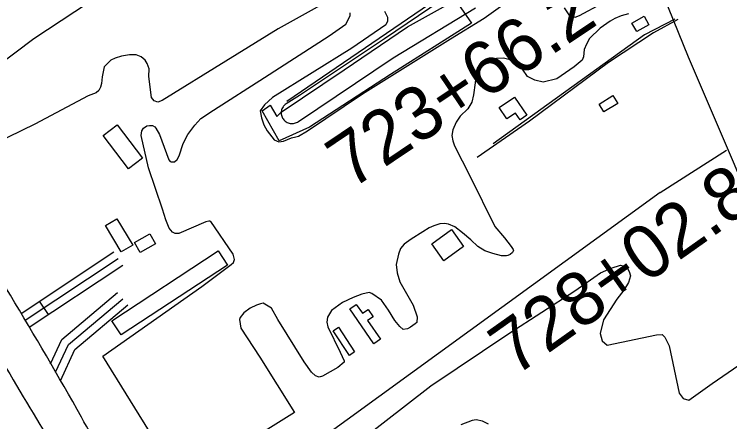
# Model space of a CAD drawing. Extents: x 3812694 to 3850888, y 319753 to 345638.
# Drawn here: x 3830119 to 3831459, y 329429 to 330193 of the extents above; entities that cross this region are included whole.
import ezdxf

# ---------------------------------------------------------------- set-up
doc = ezdxf.new("R2010")
doc.units = 0
for name, color, linetype in [('V-BLDG-OTLN', 7, 'Continuous'), ('V-RIVR-EDGE', 7, 'Continuous'), ('V-ROAD-CNTR', 7, 'Continuous'), ('V-SITE-OTLN', 7, 'Continuous'), ('V-SITE-VEGE', 7, 'Continuous'), ('V-SURV-IDEN', 7, 'Continuous')]:
    doc.layers.add(name, color=color, linetype=linetype)

msp = doc.modelspace()

# ---------------------------------------------------------------- linework, layer by layer
at = {"layer": 'V-BLDG-OTLN'}
for points in [[(3831275.7, 330176.7), (3831298.5, 330189.6), (3831307.4, 330173.8), (3831284.7, 330160.9)], [(3831027.1, 330018.4), (3831055.7, 330038.1), (3831079.1, 330004.1), (3831066.3, 329995.3), (3831057.6, 330008.1), (3831041.7, 329997.2)], [(3831214.2, 330024.8), (3831240.1, 330040.9), (3831249.2, 330026.2), (3831223.3, 330010.2)], [(3830311.3, 329985.7), (3830358.9, 329923.4), (3830333, 329903.6), (3830285.3, 329965.9)], [(3830311.2, 329809.9), (3830340.6, 329760.1), (3830319.3, 329747.6), (3830289.9, 329797.4)], [(3830383.2, 329762.9), (3830354.5, 329746.8), (3830344.1, 329765.4), (3830372.8, 329781.5)], [(3830900.8, 329762.9), (3830937.6, 329789.4), (3830960.5, 329757.6), (3830923.6, 329731.1)], [(3830301.4, 329618.5), (3830500.6, 329749.4), (3830518, 329723), (3830318.8, 329592.1)], [(3830792.2, 329575.3), (3830747.3, 329640.8), (3830759.4, 329649.2), (3830770.9, 329632.5), (3830781.5, 329639.8), (3830791, 329626), (3830780.5, 329618.7), (3830804.5, 329583.8)], [(3830725.9, 329606.2), (3830756.4, 329559.9), (3830746.7, 329553.5), (3830716.2, 329599.8)]]:
    msp.add_lwpolyline(points, close=True, dxfattribs=at)
at = {"layer": 'V-RIVR-EDGE'}
msp.add_spline([(3829949.6, 341433.3), (3829909, 341404.5), (3829896.7, 341391), (3829892.8, 341380.1), (3829894.1, 341369.2), (3829900.5, 341358.9), (3829915.9, 341346.6), (3829921.7, 341337.6), (3829921, 341333.1), (3829918.4, 341331.2), (3829912, 341326.7), (3829904.3, 341324.2), (3829899.1, 341318.4), (3829898.4, 341301.7), (3829892.6, 341285.6), (3829882.9, 341261.2), (3829881.6, 341254.1), (3829890.6, 341236.8), (3829896.3, 341218.1), (3829896.3, 341211.7), (3829892.4, 341201.4), (3829892.4, 341193.7), (3829901.4, 341182.1), (3829901.3, 341172.5), (3829893, 341166.7), (3829875.6, 341162.2), (3829873, 341162.9), (3829867.2, 341168), (3829862.1, 341168), (3829855, 341165.5), (3829853.1, 341159.7), (3829853.7, 341156.5), (3829861.4, 341150.7), (3829869.1, 341147.5), (3829873, 341139.1), (3829873.5, 341111.4), (3829871.6, 341095.4), (3829860, 341083.2), (3829845.1, 341072.3), (3829840.6, 341065.2), (3829839.9, 341028.6), (3829840.5, 341002.9), (3829841.7, 340965.6), (3829842.3, 340961.7), (3829853.2, 340960.4), (3829869.9, 340959.7), (3829881.5, 340957.8), (3829886, 340952), (3829885.3, 340946.2), (3829880.2, 340942.4), (3829875, 340939.8), (3829852.5, 340937.3), (3829835.2, 340934.8), (3829835.2, 340932.2), (3829835.8, 340913.5), (3829840.9, 340906.5), (3829855, 340903.8), (3829870.4, 340901.9), (3829873, 340896.7), (3829873, 340882.6), (3829877.3, 340830.5), (3829882.4, 340795.8), (3829886.8, 340776.5), (3829899.8, 340805.4), (3829915.3, 340838.8), (3829924.3, 340855.5), (3829927.6, 340859.3), (3829931.4, 340859.9), (3829934.6, 340853.5), (3829933.3, 340847.7), (3829915.9, 340811.8), (3829905.5, 340789.9), (3829900.3, 340768.7), (3829896.4, 340754), (3829893.8, 340747.5), (3829878.4, 340729.6), (3829844.8, 340685.9), (3829826.1, 340659), (3829817.7, 340641.6), (3829810.6, 340620.4), (3829809.3, 340607.6), (3829813.1, 340585.1), (3829819.4, 340538.1), (3829820.6, 340506.6), (3829817.3, 340484.8), (3829809.5, 340451.4), (3829804.3, 340394.2), (3829792.6, 340355.6), (3829786.1, 340326.7), (3829779.5, 340279.2), (3829769.1, 340232.3), (3829751.1, 340203.4), (3829745.2, 340186.7), (3829735.5, 340143.6), (3829724.5, 340099.9), (3829721.9, 340090.3), (3829721.8, 340080), (3829723.1, 340074.2), (3829721.8, 340063.3), (3829720.5, 340051.7), (3829713.4, 340037), (3829705.6, 340022.2), (3829694.6, 339983.7), (3829682.9, 339940), (3829666.7, 339886.6), (3829658.3, 339864.8), (3829653.1, 339845.5), (3829646, 339812.8), (3829634.9, 339751.1), (3829621.8, 339679.1), (3829615.3, 339635.4), (3829608.6, 339541.6), (3829602.1, 339483.1), (3829596.8, 339420.1), (3829595.3, 339360.3), (3829592.7, 339319.8), (3829587.4, 339286.4), (3829584.8, 339271), (3829587.3, 339247.8), (3829584.7, 339227.3), (3829583.4, 339218.9), (3829582.7, 339205.4), (3829582.7, 339190), (3829580.1, 339166.8), (3829565.1, 339096.8), (3829556.6, 339037), (3829547.5, 339005.6), (3829548.1, 338983.1), (3829543.5, 338923.9), (3829538.2, 338877.7), (3829533, 338851.3), (3829529.7, 338832.7), (3829531.6, 338807), (3829530.8, 338740.1), (3829528.8, 338691.9), (3829524.2, 338650.1), (3829522.1, 338613.5), (3829519.5, 338571.7), (3829521.3, 338541.5), (3829528.3, 338508.7), (3829530.8, 338484.9), (3829526.9, 338456.6), (3829521, 338433.5), (3829519.1, 338419.3), (3829519, 338404.6), (3829519, 338388.5), (3829518.3, 338375), (3829517.6, 338355.7), (3829506.6, 338315.2), (3829502.7, 338293.4), (3829501.3, 338256.1), (3829501.8, 338195), (3829501, 338140.4), (3829504.2, 338101.2), (3829507.9, 338071.6), (3829508.5, 338044.6), (3829509.1, 338023.4), (3829503.3, 337998.9), (3829505.1, 337982.9), (3829517.3, 337944.9), (3829520.4, 337921.8), (3829519.1, 337896), (3829516.4, 337856.8), (3829515, 337826.6), (3829515.6, 337808.6), (3829521.4, 337777.7), (3829529.6, 337729.5), (3829534.7, 337699.3), (3829533.9, 337667.8), (3829536.3, 337600.9), (3829539.5, 337564.3), (3829543.9, 337523.1), (3829561.7, 337447.9), (3829568.1, 337438.8), (3829588.6, 337427.9), (3829595, 337423.3), (3829601.5, 337415.6), (3829601.4, 337410.5), (3829600.8, 337405.3), (3829598.9, 337400.8), (3829589.2, 337393.1), (3829577, 337385.5), (3829578.2, 337375.2), (3829581.3, 337323.7), (3829586.3, 337256.9), (3829586.8, 337207.4), (3829590.5, 337151.4), (3829597.5, 337108.3), (3829600.6, 337062.7), (3829611.4, 337010.6), (3829612.6, 336980.4), (3829611.8, 336932.1), (3829610.5, 336905.8), (3829609.7, 336842.8), (3829607.7, 336799.7), (3829607.6, 336779.8), (3829610.1, 336731.6), (3829613.8, 336673.7), (3829620.7, 336617.1), (3829633.4, 336570.8), (3829639.8, 336539.3), (3829643.6, 336512.9), (3829643.5, 336484.6), (3829643.5, 336472.4), (3829645.4, 336460.2), (3829653.1, 336443.5), (3829658.1, 336410.7), (3829663.1, 336354.7), (3829666.9, 336302.6), (3829671.3, 336276.3), (3829682.8, 336233.8), (3829689.1, 336194.6), (3829705.6, 336127.7), (3829722.1, 336045.4), (3829730.4, 335995.2), (3829737.3, 335934.1), (3829738.5, 335885.9), (3829731.9, 335827.4), (3829719.5, 335770.9), (3829715, 335740), (3829714.2, 335701.4), (3829717.3, 335660.3), (3829723, 335608.2), (3829726.1, 335578), (3829741.9, 335464.8), (3829746.9, 335408.2), (3829750.6, 335350.3), (3829749.2, 335306), (3829751.6, 335235.9), (3829747.7, 335183.8), (3829748.9, 335156.2), (3829755.8, 335111.8), (3829765.4, 335062.9), (3829779.4, 335020.5), (3829790.3, 335004.4), (3829807.6, 334976.7), (3829824.2, 334954.2), (3829833.2, 334944.5), (3829842.2, 334923.9), (3829845.3, 334905.9), (3829849.7, 334851.2), (3829850.9, 334819.7), (3829850.9, 334799.2), (3829850.8, 334785), (3829851.4, 334772.8), (3829856.5, 334753.5), (3829870.6, 334721.3), (3829884, 334682.1), (3829894.2, 334634.5), (3829906.3, 334588.8), (3829922.2, 334541.8), (3829941.4, 334498.1), (3829993.8, 334355.9), (3830034, 334260.6), (3830051.9, 334223.9), (3830058.9, 334200.1), (3830066.6, 334159), (3830087.5, 334047.7), (3830093.2, 333997.5), (3830094.3, 333947.4), (3830089.7, 333899.2), (3830091, 333885), (3830093.5, 333876), (3830103.1, 333865.7), (3830108.2, 333851.6), (3830113.9, 333807.8), (3830114.5, 333787.9), (3830120.2, 333753.8), (3830127.8, 333717.8), (3830136.8, 333693.4), (3830151.5, 333669.5), (3830173.3, 333630.3), (3830203.3, 333580), (3830221.3, 333545.9), (3830241.1, 333499.6), (3830252.6, 333462.9), (3830260.9, 333453.9), (3830269.2, 333447.4), (3830273.7, 333435.9), (3830289.7, 333399.2), (3830295.4, 333381.2), (3830308.9, 333361.2), (3830333.8, 333315.5), (3830363.9, 333256.9), (3830404.2, 333168.1), (3830430.4, 333108.9), (3830467.5, 333043.9), (3830486.7, 333000.8), (3830497.6, 332968.6), (3830513.5, 332924.8), (3830539.7, 332861.8), (3830564, 332809), (3830580.6, 332764), (3830613.3, 332708.6), (3830643.3, 332648.1), (3830672.8, 332595.3), (3830690.7, 332549), (3830698.3, 332513.6), (3830707.2, 332487.2), (3830732.2, 332437), (3830750.7, 332405.5), (3830775.7, 332372.6), (3830790.4, 332341.7), (3830796.8, 332311.5), (3830807.7, 332287), (3830825.6, 332251), (3830837.7, 332207.2), (3830851.7, 332171.8), (3830893.3, 332079.2), (3830924.6, 332009), (3830958.5, 331948.5), (3830982.2, 331901.5), (3830997.5, 331863.5), (3831044.9, 331756.1), (3831073.6, 331698.8), (3831102.4, 331628.6), (3831128.6, 331584.2), (3831153.6, 331545.6), (3831180.5, 331507.6), (3831199.7, 331472.8), (3831212.5, 331446.4), (3831235.6, 331407.2), (3831254.8, 331383.3), (3831272.7, 331355), (3831300.9, 331311.2), (3831318.2, 331280.3), (3831321.4, 331265.5), (3831331.6, 331252), (3831362.4, 331210.1), (3831377.1, 331184.4), (3831391.8, 331160.6), (3831436.6, 331091), (3831464.2, 331054.3), (3831483.4, 331016.3), (3831498.7, 330979.6), (3831512.8, 330947.5), (3831528.8, 330922.4), (3831549.9, 330888.2), (3831584.5, 330837.4), (3831625.5, 330783.9), (3831671, 330729.1), (3831707.6, 330695), (3831742.2, 330661.5), (3831771.1, 330626), (3831806.3, 330579.7), (3831827.4, 330543.6), (3831844.7, 330515.3), (3831878.6, 330449), (3831906.2, 330400.1), (3831926.7, 330367.9), (3831945.9, 330331.8), (3831966.3, 330299), (3831986.2, 330261), (3832006, 330232), (3832027.2, 330199.2), (3832068.2, 330145.1), (3832106, 330103.8), (3832138.1, 330071.6), (3832152.2, 330054.2), (3832155.4, 330046.5), (3832170.1, 330036.8), (3832197.7, 330013), (3832224.6, 329982.7), (3832245.1, 329949.2), (3832259.8, 329922.8), (3832282.9, 329886.8), (3832315, 329853.2), (3832349, 329822.3), (3832370.1, 329803.6), (3832377.2, 329793.9), (3832382.9, 329777.9), (3832387.4, 329766.9), (3832398.3, 329761.1), (3832406.6, 329750.8), (3832417.5, 329729.6), (3832428.4, 329712.2), (3832437.4, 329699.3), (3832461.7, 329674.2)], degree=3, dxfattribs=at)
at = {"layer": 'V-ROAD-CNTR'}
msp.add_line((3830165.7, 329655), (3830182.3, 329630), dxfattribs=at)
for points in [[(3831242.5, 330449.4), (3830629.2, 330030)], [(3831315.8, 330275.9), (3831381.1, 330113.3), (3831465.3, 329916.8), (3831531.3, 329758.4), (3831618.7, 329567), (3831726.4, 329313.3), (3831843.5, 329079.2)], [(3830961, 330248.7), (3830812.1, 330147.3), (3830653.1, 330041), (3830627.9, 330025.3), (3830626.2, 330024.1), (3830624.7, 330022.8), (3830623.4, 330021.3), (3830622.2, 330019.7), (3830621.1, 330018), (3830620.3, 330016.2), (3830619.6, 330014.3), (3830619.1, 330012.3), (3830618.8, 330010.3), (3830618.8, 330009.6), (3830618.7, 330008.3), (3830618.9, 330006.3), (3830619.2, 330004.3), (3830619.7, 330002.4), (3830620.4, 330000.5), (3830621.3, 329998.7), (3830622.4, 329997), (3830623.6, 329995.4), (3830625, 329993.9), (3830626.5, 329992.6), (3830628.2, 329991.5), (3830629.9, 329990.5), (3830631.8, 329989.7), (3830633.7, 329989.1), (3830635.6, 329988.6), (3830637.6, 329988.4), (3830639.7, 329988.4), (3830641.7, 329988.6), (3830643.6, 329989), (3830645.6, 329989.5), (3830647.4, 329990.3), (3830649.2, 329991.3), (3830650.9, 329992.4), (3830828.4, 330111.4), (3830982.8, 330205.3)], [(3831361.8, 330183.6), (3831316.3, 330158.7), (3831232.2, 330103), (3831083.9, 329992.6), (3830985.7, 329924.9)], [(3831356.3, 330184.5), (3831299.2, 330155.1), (3831015.6, 329950.2)], [(3831328.9, 329859.2), (3831452.8, 329938.2)], [(3831328.9, 329859.2), (3830445.5, 329217), (3830295.2, 329110.1)], [(3830131.5, 329632.3), (3830305.3, 329747.8)], [(3830139.1, 329619.3), (3830313.6, 329735.3)], [(3830146.6, 329606.3), (3830321.9, 329722.8)], [(3830186.7, 329537.6), (3830207.9, 329583.1), (3830312.4, 329671.4)], [(3830195.9, 329521.8), (3830220.1, 329573.8), (3830322.1, 329659.9)], [(3830205.1, 329506), (3830232.3, 329564.4), (3830331.8, 329648.5)]]:
    msp.add_lwpolyline(points, dxfattribs=at)
for points in [[(3831241.8, 327435.3), (3831117.8, 327719.5), (3830988.9, 328002.1), (3830839.5, 328315.6), (3830712, 328572.3), (3830592.5, 328806), (3830474.6, 329023), (3830398.3, 329180.7), (3830323.9, 329299.3), (3830244.5, 329437.9), (3830111.5, 329666.4), (3829978, 329888.9), (3829858.2, 330096.3)], [(3829794.8, 330052.8), (3829924, 329831), (3830129.5, 329486.4), (3830326.4, 329153.4), (3830446, 328946.8), (3830574.2, 328720.2), (3830782.3, 328334), (3830932.5, 328031.3), (3831093.7, 327679.5), (3831210.6, 327423)]]:
    msp.add_spline(points, degree=3, dxfattribs=at)
at = {"layer": 'V-SITE-OTLN'}
msp.add_lwpolyline([(3830975, 330176.7), (3830823.4, 330080.1), (3830671.9, 329981.7), (3830615.2, 329956.1), (3830583.1, 330012.2), (3830598.4, 330023), (3830610.5, 330001.8), (3830618.8, 330009.6), (3830736.7, 330089.3), (3830855.1, 330169.5), (3830945.4, 330220.4)], close=True, dxfattribs=at)
at = {"layer": 'V-SITE-VEGE'}
for points in [[(3830010.2, 330038.4), (3830155.5, 330148.1), (3830334.4, 330267)], [(3830812.6, 330199.5), (3830818.1, 330187.8), (3830818.1, 330180.7), (3830814.7, 330173.6), (3830751.3, 330129.7), (3830602.2, 330037.1), (3830587.6, 330023.4), (3830579.3, 330012.3), (3830582, 329999), (3830586, 329986.1), (3830592.4, 329974.7), (3830605.9, 329957.8), (3830614.5, 329954.2), (3830623, 329955.2), (3830637.9, 329961.3), (3830646.2, 329963.2), (3830650.9, 329965), (3830667.9, 329974.6), (3830770.9, 330043.9), (3830936, 330147.2), (3830998.9, 330186.1), (3831086.2, 330249.2)], [(3831148.8, 330205.6), (3831157.8, 330192.1), (3831169.6, 330188.1), (3831177.3, 330191.1), (3831261.3, 330236.9)], [(3830708.4, 330219.1), (3830613.3, 330166.1), (3830515.2, 330105.3), (3830396.1, 330031.9), (3830387.9, 330028.3), (3830380.7, 330031.2), (3830375.9, 330037), (3830370.8, 330076.6), (3830371.2, 330091.3), (3830367.6, 330101.3), (3830364, 330107.2), (3830356.8, 330113.6), (3830347.3, 330117.1), (3830334.9, 330117.5), (3830319.6, 330115), (3830307.8, 330111.3), (3830299.6, 330107.1), (3830291.9, 330099.9), (3830287.3, 330094.6), (3830286.2, 330088.6), (3830283.3, 330076.2), (3830282.3, 330063.8), (3830280.6, 330056.7), (3830277.1, 330050.1), (3830272.4, 330046), (3830257.1, 330040.5), (3830157.3, 329987.4), (3830055.6, 329937.8)], [(3830944.1, 329794.5), (3830932.2, 329799.6), (3830924.5, 329800.7), (3830916.2, 329800.1), (3830904.4, 329796.4), (3830896.2, 329792.7), (3830883.9, 329785.5), (3830862.2, 329771.7), (3830849.3, 329762.1), (3830842.3, 329754.3), (3830838.3, 329743.1), (3830834.3, 329724.1), (3830836.3, 329708.2), (3830841.2, 329691.7), (3830865.9, 329647.7), (3830873.8, 329625.9), (3830872.7, 329615.2), (3830869.8, 329612.8), (3830861, 329606.2), (3830855.1, 329603.2), (3830847.5, 329602), (3830840.9, 329607.8), (3830831.9, 329618.9), (3830819.9, 329638.3), (3830806.7, 329657.1), (3830788.8, 329669.9), (3830783.5, 329671.6), (3830769.9, 329668.5), (3830753.5, 329662.4), (3830733.5, 329652.7), (3830713, 329637.7), (3830705.4, 329625.2), (3830704.3, 329615.8), (3830706.2, 329606.9), (3830729.2, 329559.3), (3830737, 329543.4), (3830736.5, 329540.5), (3830724.7, 329530.9), (3830696, 329514.6), (3830690.1, 329512.8), (3830683, 329515.1), (3830675.8, 329522.1), (3830662, 329541.4), (3830612.7, 329620.7), (3830600.6, 329642.4), (3830585.2, 329651.7), (3830579.9, 329650.5), (3830572.8, 329648), (3830560.5, 329642), (3830548.7, 329633.6), (3830541.7, 329624.6), (3830540.6, 329621.1), (3830543.1, 329604.6), (3830578.6, 329550), (3830643.5, 329446.7), (3830432.3, 329313.8), (3830284.9, 329552.1), (3830470.2, 329682.9), (3830525.3, 329723.7), (3830529.4, 329727.9), (3830531.1, 329733.2), (3830528.6, 329743.3), (3830487.2, 329804.8), (3830485.4, 329805.4), (3830483.1, 329805.4), (3830477.7, 329804.2), (3830427.2, 329782.3), (3830420.1, 329782.3), (3830415.3, 329784.6), (3830408.7, 329792.2), (3830402.7, 329807.5), (3830396.5, 329828.1), (3830370.3, 329905.2), (3830356.6, 329965.9), (3830357.7, 329974.8), (3830360.6, 329979.5), (3830367.1, 329983.8), (3830372.4, 329985), (3830377.7, 329984.5), (3830381.9, 329982.1), (3830384.2, 329979.8), (3830390.9, 329968.1), (3830408.5, 329920.4), (3830410.9, 329916.9), (3830412.7, 329916.3), (3830419.2, 329916.4), (3830423.9, 329921.2), (3830427.4, 329927.7), (3830435.4, 329950.8), (3830444.1, 329968), (3830456.9, 329985.3), (3830468, 329997.9), (3830492, 330013.5), (3830587.7, 330074.8), (3830708.5, 330152.9), (3830739.6, 330175.1), (3830747.7, 330190.6), (3830748.2, 330195.9)], [(3831269.4, 330193.9), (3831255.9, 330190.2), (3831243.5, 330185.3), (3831235.3, 330180.5), (3831216.5, 330167.3), (3831196.6, 330148.2), (3831190.9, 330137.5), (3831186.2, 330127.4), (3831185.2, 330113.8), (3831182.3, 330107.3), (3831167.7, 330094.7), (3831135.4, 330072.5), (3831109.5, 330066.3), (3831094.1, 330069.7), (3831080.4, 330076.6), (3831070.8, 330090.7), (3831064.8, 330098.9), (3831055.9, 330104.7), (3831047.6, 330108.2), (3831035.1, 330111), (3831022.2, 330110.2), (3831005.1, 330106.5), (3830992.1, 330101), (3830986.3, 330093.3), (3830984.6, 330088), (3830981.9, 330064.9), (3830979.2, 330042.4), (3830975.8, 330028.2), (3830968.2, 330016.3), (3830954.2, 330002), (3830946.6, 329991.2), (3830940.3, 329976.4), (3830938.6, 329965.7), (3830940.5, 329955.7), (3830943.6, 329946.3), (3830972, 329890.5), (3831019.1, 329795.3), (3831037, 329774.2), (3831049.6, 329757.8), (3831053.2, 329751.9), (3831053.8, 329750.1), (3831052.1, 329746.6), (3831048, 329743), (3831043.3, 329740.6), (3831041, 329740), (3831031.5, 329740.5), (3831015.5, 329744.4), (3831000.1, 329749.6), (3830987, 329757.7), (3830973.9, 329770), (3830958.4, 329783.4), (3830944.1, 329794.5)], [(3830768.2, 329394.3), (3830898.8, 329496.2), (3831044.9, 329594.7), (3831168.7, 329674.6), (3831216.8, 329708.2), (3831236.8, 329717.3), (3831254.5, 329722.8), (3831265.7, 329720), (3831270.5, 329711.1), (3831273, 329702.9), (3831269.6, 329690.5), (3831260.9, 329675.6), (3831247.5, 329658.9), (3831222.5, 329620.2), (3831216.3, 329594.7), (3831220, 329580.6), (3831229.5, 329573), (3831322, 329592.3), (3831332.7, 329592.5), (3831337.5, 329587.8), (3831345.3, 329571.3), (3831364, 329482.9), (3831371.8, 329472.9), (3831382.5, 329469.5), (3831425.9, 329500.7), (3831537.9, 329577.6)], [(3831007.2, 329424.7), (3830995.9, 329430.4), (3830984, 329432.7), (3830976.4, 329431.4), (3830955.2, 329423.5)]]:
    msp.add_lwpolyline(points, dxfattribs=at)

# ---------------------------------------------------------------- texts
at = {"layer": 'V-SURV-IDEN'}
for s, rotation, p in [('723+66.2', 33.9013, (3830749.1, 329863.2)), ('728+02.8', 35.3447, (3831055.8, 329512.2))]:
    msp.add_text(s, height=100, rotation=rotation, dxfattribs=at).set_placement(p)

doc.saveas('drawing.dxf')
